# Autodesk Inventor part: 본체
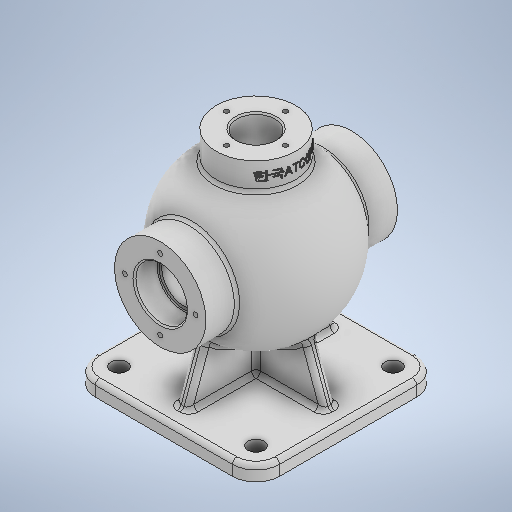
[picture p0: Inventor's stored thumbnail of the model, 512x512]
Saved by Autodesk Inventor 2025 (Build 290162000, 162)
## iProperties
Created: 2024-07
Part Number: 본체
Material: 일반
Document SubType Name: Modeling
Designer: myung
Density: 1 g/cm^3
Appearance: 기본값
Mass: 565.461 g
Surface Area: 1174.07 cm^2
Volume: 565.461 cm^3
Author: myung
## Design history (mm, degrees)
sketch "스케치1"
  geometry: L1 (62.5, 62.5)-(-62.5, 62.5); L2 (-62.5, 62.5)-(-62.5, -62.5); L3 (-62.5, -62.5)-(62.5, -62.5); L4 (62.5, -62.5)-(62.5, 62.5); L5 (62.5, 62.5)-(-62.5, -62.5); L6 (-62.5, 62.5)-(62.5, -62.5); 1 further point
  constraints: 12 end point, 2 midpoint, 2 parallel, 1 horizontal, 1 perpendicular
  dimensions: "d0" = 125 distance of L3.end L1.start; "d1" = 125 distance of L2.end L3.end
extrude "돌출1" new body sketch "스케치1" distance "d2" = 10; taper "d3" = 0 deg
sketch "스케치2"
  geometry: L1 (-15.639, 85)-(20.037, 85); L2 (0, 139)-(0, 31); A1 r 54 centre (0, 85) between (0, 31) and (0, 139); 1 further point
  constraints: 4 end point, 2 point on circle, 1 centre point, 1 horizontal, 1 midpoint, 1 point on line, 1 vertical, 1 vertical alignment
  dimensions: "d4" = 85 distance from line of L1 point (0, 0); "d5" = 108 diameter of A1
revolve "회전1" sketch "스케치2" stored, may be unused: angle "d6" = 90 deg
sketch "스케치3"
  geometry: C1 r 54 at (0, 85) reference; C2 r 31 at (0, 85); 1 further point
  constraints: 1 centre point, 1 coincident
  dimensions: "d7" = 62 diameter of C2
extrude "돌출2" join sketch "스케치3" stored distance "d8" = 130; taper "d9" = 0 deg
node "작업 평면1"
sketch "스케치4"
  geometry: C1 r 27 at (0, 0); 1 further point
  constraints: 1 centre point, 1 coincident
  dimensions: "d11" = 54 diameter of C1
extrude "돌출3" join sketch "스케치4" stored distance "d12" = 10; taper "d13" = 0 deg
sketch "스케치5"
  geometry: L1 (37.385, 46.034)-(50.5, 10); L2 (-37.385, 46.034)-(-50.5, 10); L3 (-62.5, 0)-(-62.5, 10) reference; L4 (62.5, 10)-(-62.5, 10) reference; L5 (62.5, 0)-(62.5, 10) reference; L6 (-37.385, 46.034)-(37.385, 46.034); L7 (-50.5, 10)-(50.5, 10); A1 r 54 centre (0, 85) between (-27, 131.765) and (27, 131.765) reference; 1 further point
  constraints: 8 end point, 2 point on line, 1 collinear, 1 horizontal, 1 point on circle
  dimensions: "d14" = 12 distance from line of L3 L2.end; "d15" = 20 deg angle of L3 L2; "d16" = 12 distance from line of L5 L1.end; "d17" = 20 deg angle of L5 L1
extrude "돌출4" join sketch "스케치5" stored distance "d18" = 8; taper "d19" = 0 deg
sketch "스케치6" dims "d15" = 20 deg
  geometry: L1 (46.034, -37.385)-(10, -50.5); L2 (0, -62.5)-(10, -62.5) reference; L3 (10, -62.5)-(10, 62.5) reference; L4 (46.034, 37.385)-(10, 50.5); L5 (0, 62.5)-(10, 62.5) reference; L6 (46.034, 37.385)-(46.034, -37.385); L7 (10, 50.5)-(10, -50.5); A1 r 54 centre (85, 0) between (54, 44.215) and (116, 44.215) reference; 1 further point
  constraints: 8 end point, 2 point on circle, 2 point on line, 1 collinear
  dimensions: "d20" = 12 distance from line of L2 L1.end; "d21" = 20 deg angle of L2 L1; "d22" = 12 distance from line of L5 L4.end; "d23" = 20 deg angle of L5 L4
extrude "돌출5" join sketch "스케치6" stored distance "d24" = 8; taper "d25" = 0 deg
fillet "모깎기1" dims "d26" = 16
fillet "모깎기2" dims "d27" = 3
fillet "모깎기3" dims "d28" = 3
fillet "모깎기4" dims "d29" = 3
fillet "모깎기5" dims "d30" = 3
sketch "스케치7"
  geometry: L1 (0, 41)-(0, 129); L2 (6.632, 45.054)-(6.632, 31.821) reference; A1 r 54 centre (0, 85) between (37.385, 46.034) and (-37.385, 46.034) reference; A2 r 44 centre (0, 85) between (0, 41) and (0, 129); 1 further point
  constraints: 3 point on circle, 2 end point, 1 centre point, 1 coincident, 1 midpoint, 1 parallel
  dimensions: "d31" = 44 radius of A2
revolve "회전2" sketch "스케치7" stored, may be unused: angle "d32" = 90 deg
sketch "스케치8"
  geometry: C1 r 13 at (0, 0); 1 further point
  constraints: 1 centre point, 1 coincident
  dimensions: "d33" = 26 diameter of C1
extrude "돌출6" cut sketch "스케치8" stored distance "d34" = 8; taper "d35" = 0 deg
sketch "스케치9"
  geometry: C1 r 31 at (0, 0) reference; C2 r 17.5 at (0, 0); 1 further point
  constraints: 1 centre point, 1 coincident
  dimensions: "d36" = 35 diameter of C2
extrude "돌출7" cut sketch "스케치9" distance "d37" = 16; taper "d38" = 0 deg
extrude "돌출8" cut sketch "스케치9" stored distance "d39" = 16; taper "d40" = 0 deg
chamfer "모따기1" distance "d41" = 1; stored, may be unused: second distance "d42" = 2, angle "d43" = 45 deg
fillet "모깎기6" dims "d44" = 0.6
sketch "스케치10"
  geometry: C1 r 31 at (0, 0) reference; C2 r 15 at (0, 0); 1 further point
  constraints: 1 centre point, 1 coincident
  dimensions: "d45" = 30 diameter of C2
extrude "돌출9" cut sketch "스케치10" stored distance "d46" = 16; taper "d47" = 0 deg
sketch "스케치11"
  geometry: C1 r 31 at (0, 0) reference; C2 r 15 at (0, 0); 1 further point
  constraints: 1 centre point, 1 coincident
  dimensions: "d48" = 30 diameter of C2
extrude "돌출10" cut sketch "스케치11" stored distance "d49" = 10; taper "d50" = 0 deg
chamfer "모따기2" distance "d51" = 1; stored, may be unused: second distance "d52" = 2, angle "d53" = 45 deg
sketch "스케치12"
  geometry: C1 r 31 at (0, 0) reference; A1 r 24 centre (0, 0) between (0, 24) and (0, -24); 3 further points
  constraints: 4 point on circle, 2 horizontal alignment, 2 vertical alignment, 1 centre point, 1 coincident
  dimensions: "d61" = 48 diameter of A1
hole "구멍1" sketch "스케치12" at (0, 24), (0, -24), (24, 0), (-24, 0) diameter "d54" = 3.242; stored, may be unused: countersink angle "d58" = 90 deg, drill point angle "d60" = 120 deg; dims "d55" = 12, "d56" = 4, "d57" = 2, "d59" = 15
sketch "스케치13"
  geometry: C1 r 31 at (0, 0) reference; A1 r 24 centre (0, 0) between (0, 24) and (0, -24); 3 further points
  constraints: 4 point on circle, 2 horizontal alignment, 2 vertical alignment, 1 centre point, 1 coincident
  dimensions: "d69" = 48 diameter of A1
hole "구멍2" sketch "스케치13" at (0, -24), (0, 24), (24, 0), (-24, 0) diameter "d62" = 3.242; stored, may be unused: countersink angle "d66" = 90 deg, drill point angle "d68" = 120 deg; dims "d63" = 12, "d64" = 4, "d65" = 2, "d67" = 15
sketch "스케치14"
  geometry: C1 r 27 at (0, 0) reference; A1 r 20 centre (0, 0) between (-20, 0) and (0, -20); 3 further points
  constraints: 4 point on circle, 2 horizontal alignment, 2 vertical alignment, 1 centre point, 1 coincident
  dimensions: "d77" = 40 diameter of A1
hole "구멍3" sketch "스케치14" at (-20, 0), (20, 0), (0, 20), (0, -20) diameter "d70" = 3.242; stored, may be unused: countersink angle "d74" = 90 deg, drill point angle "d76" = 120 deg; dims "d71" = 9, "d72" = 4, "d73" = 2, "d75" = 11
sketch "스케치15"
  geometry: A1 r 13 centre (46.5, -46.5) between (46.5, -59.5) and (59.5, -46.5) reference; A2 r 13 centre (46.5, 46.5) between (59.5, 46.5) and (46.5, 59.5) reference; A3 r 13 centre (-46.5, 46.5) between (-46.5, 59.5) and (-59.5, 46.5) reference; A4 r 13 centre (-46.5, -46.5) between (-59.5, -46.5) and (-46.5, -59.5) reference; 5 further points
  constraints: 4 coincident
hole "구멍4" sketch "스케치15" at (46.5, -46.5), (46.5, 46.5), (-46.5, 46.5), (-46.5, -46.5) diameter "d78" = 11; stored, may be unused: countersink angle "d82" = 90 deg, drill point angle "d84" = 0 deg; dims "d79" = 6, "d80" = 4, "d81" = 2, "d83" = 8
fillet "모깎기7" dims "d85" = 3
node "작업 평면2"
sketch "스케치16"
  geometry: L1 (150, -27)-(150, 27) reference; 2 further points
  constraints: 1 horizontal alignment, 1 other
  dimensions: "d87" = 9 distance from line of L1 point (141, 0)
feature "엠보싱1" sketch "스케치16" dims "d0" = 125, "d1" = 125, "d88" = 0.5, "d89" = 0
node "솔리드1"
feature "A9D066F2-1C7D-4E18-AEED-F7BC21143FA4" dims "d54" = 3.242, "d55" = 12, "d56" = 4, "d57" = 2, "d58" = 90 deg, "d59" = 15, "d60" = 120 deg
other parameters: "d86" = 136.25
